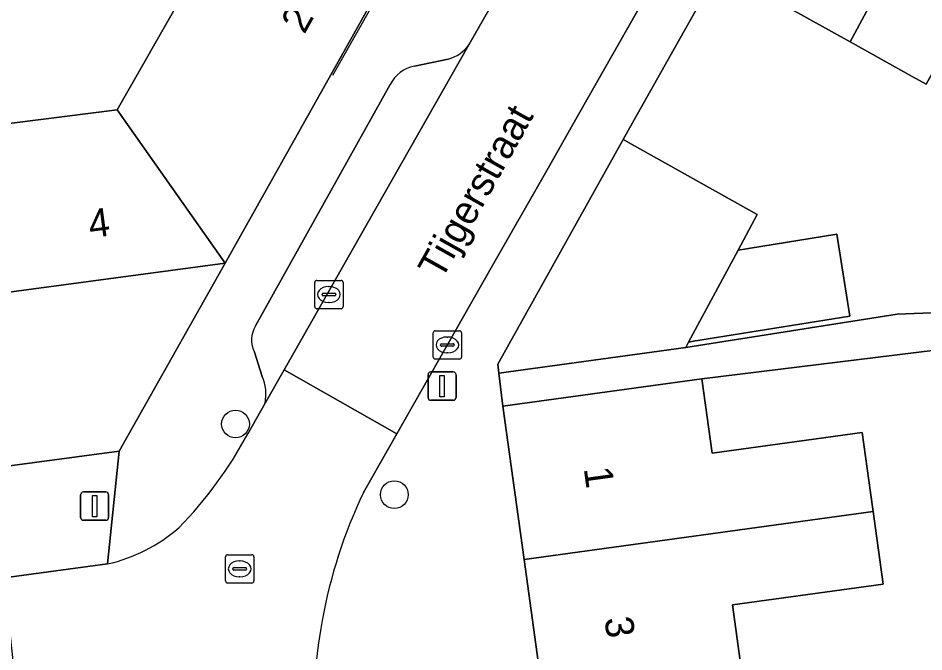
# Model space of a CAD drawing. Extents: x 163147 to 163550, y 380933 to 381639.
# Drawn here: x 163383.31 to 163415.28, y 381494.38 to 381516.74 of the extents above; entities that cross this region are included whole.
import ezdxf

# ---------------------------------------------------------------- set-up
doc = ezdxf.new("R2010")
doc.units = 0
for name, color, linetype in [('IMGEO_Boom', 7, 'Continuous'), ('IMGEO_Erf', 7, 'Continuous'), ('IMGEO_Kolk', 7, 'Continuous'), ('IMGEO_Lichtmast', 7, 'Continuous'), ('IMGEO_Muur', 7, 'Continuous'), ('IMGEO_Openbare_ruimte_label', 7, 'Continuous'), ('IMGEO_Pand', 7, 'Continuous'), ('IMGEO_Pand_nummerreeks', 7, 'Continuous'), ('IMGEO_Parkeervlak_open', 7, 'Continuous'), ('IMGEO_Rijbaan_lokaal_open', 7, 'Continuous'), ('IMGEO_Rioolput', 7, 'Continuous'), ('IMGEO_Voetpad_open', 7, 'Continuous')]:
    doc.layers.add(name, color=color, linetype=linetype)

msp = doc.modelspace()

# ---------------------------------------------------------------- linework, layer by layer
at = {"layer": 'IMGEO_Boom'}
for centre in [(163390.984, 381502.417), (163396.588, 381499.924)]:
    msp.add_circle(centre, 0.489, dxfattribs=at)
at = {"layer": 'IMGEO_Erf'}
for points in [[(163290.692, 381502.077), (163296.934, 381502.909), (163303.175, 381503.742), (163309.37, 381504.568), (163317.378, 381505.636), (163320.439, 381506.043), (163328.504, 381507.143), (163334.606, 381507.974), (163340.83, 381508.823), (163347.054, 381509.671), (163353.278, 381510.52), (163359.502, 381511.368), (163365.726, 381512.217), (163371.951, 381513.065), (163378.25, 381513.924), (163378.437, 381512.446), (163386.81, 381513.506), (163391.494, 381521.713), (163396.616, 381518.793), (163399.995, 381524.821), (163394.095, 381528.2), (163395.21, 381530.178), (163389.772, 381533.219)], [(163410.272, 381522.434), (163405.156, 381513.335), (163404.666, 381512.456), (163409.399, 381509.817), (163408.72, 381508.556), (163409.018, 381508.603), (163409.088, 381508.615), (163412.202, 381509.113), (163412.665, 381506.223), (163407.37, 381505.375), (163407.307, 381505.365), (163407.203, 381505.348), (163406.974, 381505.312), (163406.872, 381505.122), (163407.094, 381505.153), (163414.331, 381506.299), (163417.656, 381506.427)], [(163418.659, 381520.343), (163415.352, 381514.411), (163414.86, 381514.686), (163412.675, 381515.904), (163410.492, 381517.121)], [(163386.878, 381501.46), (163390.622, 381508.099), (163381.921, 381506.929), (163382.408, 381503.275), (163379.644, 381502.906), (163373.418, 381502.075), (163367.191, 381501.244), (163360.965, 381500.413), (163354.738, 381499.581), (163348.512, 381498.75), (163342.285, 381497.919), (163336.059, 381497.088), (163336.166, 381496.323), (163331.126, 381495.675), (163330.852, 381497.601), (163329.792, 381497.46), (163321.723, 381496.388), (163321.893, 381494.988), (163321.919, 381494.8)], [(163416.346, 381505.106), (163407.444, 381504.011), (163407.806, 381501.386), (163413.097, 381502.115), (163413.393, 381500), (163413.486, 381499.333), (163413.844, 381496.769), (163408.52, 381496.035), (163408.91, 381493.202), (163413.394, 381493.954), (163419.82, 381493.713)], [(163323.398, 381493.128), (163323.846, 381493.024), (163386.878, 381501.46)]]:
    msp.add_lwpolyline(points, dxfattribs=at)
at = {"layer": 'IMGEO_Kolk'}
for p, q in [((163393.781, 381506.561), (163393.781, 381507.413)), ((163393.856, 381507.487), (163394.708, 381507.487)), ((163394.782, 381507.413), (163394.782, 381506.561)), ((163394.269, 381507.267), (163394.294, 381507.267)), ((163394.04, 381506.981), (163394.04, 381506.993)), ((163394.478, 381506.944), (163394.08, 381506.944)), ((163394.083, 381507.03), (163394.481, 381507.03)), ((163394.524, 381506.993), (163394.524, 381506.981)), ((163394.708, 381506.487), (163393.856, 381506.487)), ((163394.292, 381506.707), (163394.267, 381506.707)), ((163397.961, 381504.782), (163397.961, 381505.634)), ((163398.036, 381505.708), (163398.888, 381505.708)), ((163398.449, 381505.488), (163398.474, 381505.488)), ((163398.962, 381505.634), (163398.962, 381504.782)), ((163398.22, 381505.202), (163398.22, 381505.214)), ((163398.658, 381505.165), (163398.26, 381505.165)), ((163398.263, 381505.251), (163398.661, 381505.251)), ((163398.704, 381505.214), (163398.704, 381505.202)), ((163398.472, 381504.928), (163398.447, 381504.928)), ((163398.888, 381504.708), (163398.036, 381504.708))]:
    msp.add_line(p, q, dxfattribs=at)
for points in [[(163393.781, 381506.561), (163393.781, 381507.413)], [(163393.856, 381507.487), (163394.708, 381507.487)], [(163394.782, 381507.413), (163394.782, 381506.561)], [(163394.708, 381506.487), (163393.856, 381506.487)], [(163397.961, 381504.782), (163397.961, 381505.634)], [(163398.036, 381505.708), (163398.888, 381505.708)], [(163398.962, 381505.634), (163398.962, 381504.782)], [(163398.888, 381504.708), (163398.036, 381504.708)]]:
    msp.add_lwpolyline(points, dxfattribs=at)
for centre, radius, start, end in [((163393.858, 381507.411), 0.0765, 91.552, 178.448), ((163393.858, 381507.411), 0.0765, 91.552, 178.448), ((163394.706, 381507.411), 0.0765, 1.552, 88.448), ((163394.706, 381507.411), 0.0765, 1.552, 88.448), ((163394.08, 381506.99), 0.0403, 85.8775, 175.7526), ((163394.077, 381506.98), 0.0366, 178.938, 274.7102), ((163394.481, 381506.987), 0.043, 264.8664, 352.4533), ((163394.485, 381506.992), 0.0386, 1.7309, 96.639), ((163393.858, 381506.563), 0.0765, 181.552, 268.448), ((163393.858, 381506.563), 0.0765, 181.552, 268.448), ((163394.706, 381506.563), 0.0765, 271.552, 358.448), ((163394.706, 381506.563), 0.0765, 271.552, 358.448), ((163398.038, 381505.632), 0.0765, 91.552, 178.448), ((163398.038, 381505.632), 0.0765, 91.552, 178.448), ((163398.886, 381505.632), 0.0765, 1.552, 88.448), ((163398.886, 381505.632), 0.0765, 1.552, 88.448), ((163398.26, 381505.211), 0.0403, 85.8775, 175.7526), ((163398.257, 381505.201), 0.0366, 178.938, 274.7102), ((163398.661, 381505.208), 0.043, 264.8664, 352.4533), ((163398.665, 381505.213), 0.0386, 1.7309, 96.639), ((163398.038, 381504.784), 0.0765, 181.552, 268.448), ((163398.038, 381504.784), 0.0765, 181.552, 268.448), ((163398.886, 381504.784), 0.0765, 271.552, 358.448), ((163398.886, 381504.784), 0.0765, 271.552, 358.448)]:
    msp.add_arc(centre, radius, start, end, dxfattribs=at)
for centre, major_axis, ratio, start_param, end_param in [((163394.268, 381506.987), (-0.387, 0.002), 0.722429, 4.712389, 7.853982), ((163394.293, 381506.987), (-0.39, 0.002), 0.717154, 1.570796, 4.712389), ((163398.448, 381505.208), (-0.387, 0.002), 0.722429, 4.712389, 7.853982), ((163398.473, 381505.208), (-0.39, 0.002), 0.717154, 1.570796, 4.712389)]:
    msp.add_ellipse(centre, major_axis=major_axis, ratio=ratio, start_param=start_param, end_param=end_param, dxfattribs=at)
at = {"layer": 'IMGEO_Lichtmast'}
for p, q in [((163397.881, 381504.256), (163398.671, 381504.256)), ((163398.671, 381504.256), (163397.881, 381504.256)), ((163397.781, 381503.356), (163397.781, 381504.156)), ((163397.781, 381504.156), (163397.781, 381503.356)), ((163398.771, 381504.156), (163398.771, 381503.356)), ((163398.771, 381503.356), (163398.771, 381504.156)), ((163398.671, 381503.256), (163397.881, 381503.256)), ((163397.881, 381503.256), (163398.671, 381503.256)), ((163385.516, 381499.121), (163385.516, 381499.921)), ((163385.516, 381499.921), (163385.516, 381499.121)), ((163385.616, 381500.021), (163386.406, 381500.021)), ((163386.406, 381500.021), (163385.616, 381500.021)), ((163386.506, 381499.921), (163386.506, 381499.121)), ((163386.506, 381499.121), (163386.506, 381499.921)), ((163386.406, 381499.021), (163385.616, 381499.021)), ((163385.616, 381499.021), (163386.406, 381499.021))]:
    msp.add_line(p, q, dxfattribs=at)
for points in [[(163398.201, 381504.131), (163398.351, 381504.131), (163398.351, 381503.381), (163398.201, 381503.381), (163398.201, 381504.131)], [(163385.936, 381499.896), (163386.086, 381499.896), (163386.086, 381499.146), (163385.936, 381499.146), (163385.936, 381499.896)]]:
    msp.add_lwpolyline(points, dxfattribs=at)
for centre, start, end in [((163397.881, 381504.156), 90, 180), ((163397.881, 381504.156), 90, 180), ((163398.671, 381504.156), 0, 90), ((163398.671, 381504.156), 360, 90), ((163397.881, 381503.356), 180, 270), ((163397.881, 381503.356), 180, 270), ((163398.671, 381503.356), 270, 0), ((163398.671, 381503.356), 270, 0), ((163385.616, 381499.921), 90, 180), ((163385.616, 381499.921), 90, 180), ((163386.406, 381499.921), 0, 90), ((163386.406, 381499.921), 360, 90), ((163385.616, 381499.121), 180, 270), ((163385.616, 381499.121), 180, 270), ((163386.406, 381499.121), 270, 0), ((163386.406, 381499.121), 270, 0)]:
    msp.add_arc(centre, 0.1, start, end, dxfattribs=at)
at = {"layer": 'IMGEO_Muur'}
for points in [[(163405.156, 381513.335), (163410.272, 381522.434)], [(163394.422, 381514.725), (163396.264, 381518.003)]]:
    msp.add_lwpolyline(points, dxfattribs=at)
at = {"layer": 'IMGEO_Pand'}
for points in [[(163412.675, 381515.904), (163418.679, 381527.058), (163414.231, 381529.537), (163410.272, 381522.434), (163412.7, 381521.08), (163410.492, 381517.121)], [(163418.679, 381527.058), (163412.675, 381515.904), (163414.86, 381514.686), (163415.352, 381514.411), (163418.659, 381520.343), (163421.229, 381518.91), (163425.443, 381526.737), (163420.55, 381529.464), (163419.083, 381526.833)], [(163396.616, 381518.793), (163391.494, 381521.713), (163386.81, 381513.506), (163390.622, 381508.099)], [(163386.81, 381513.506), (163378.437, 381512.446), (163379.644, 381502.906), (163382.408, 381503.275), (163381.921, 381506.929), (163390.622, 381508.099)], [(163404.666, 381512.456), (163400.246, 381504.532), (163400.279, 381504.213), (163406.872, 381505.122), (163406.974, 381505.312), (163408.72, 381508.556), (163409.399, 381509.817)], [(163408.72, 381508.556), (163406.974, 381505.312), (163407.203, 381505.348), (163407.307, 381505.365), (163407.37, 381505.375), (163412.665, 381506.223), (163412.202, 381509.113), (163409.088, 381508.615), (163409.018, 381508.603)], [(163401.169, 381497.642), (163413.486, 381499.333), (163413.393, 381500), (163413.097, 381502.115), (163407.806, 381501.386), (163407.444, 381504.011), (163405.378, 381503.726), (163400.424, 381503.043), (163400.844, 381500)], [(163401.169, 381497.642), (163401.915, 381492.238), (163406.869, 381492.921), (163408.91, 381493.202), (163408.52, 381496.035), (163413.844, 381496.769), (163413.486, 381499.333)]]:
    msp.add_lwpolyline(points, close=True, dxfattribs=at)
at = {"layer": 'IMGEO_Parkeervlak_open'}
for points in [[(163392.026, 381503.156), (163392.697, 381504.335), (163399.217, 381515.793)], [(163398.491, 381515.293), (163397.3, 381515.05)], [(163396.445, 381514.395), (163391.695, 381505.878)], [(163391.651, 381504.952), (163391.925, 381504.1)]]:
    msp.add_lwpolyline(points, dxfattribs=at)
for centre, radius, start, end in [((163398.137, 381516.585), 1.339, 285.3429, 323.7679), ((163397.524, 381513.872), 1.199, 100.7741, 154.1361), ((163392.49, 381505.376), 0.941, 147.7537, 206.8055), ((163390.557, 381503.476), 1.503, 347.6991, 24.5148)]:
    msp.add_arc(centre, radius, start, end, dxfattribs=at)
at = {"layer": 'IMGEO_Rijbaan_lokaal_open'}
msp.add_lwpolyline([(163414.262, 381532.989), (163414.654, 381533.678), (163410.599, 381535.956), (163409.219, 381533.373), (163408.677, 381532.42), (163400.477, 381518.009), (163399.217, 381515.793), (163392.697, 381504.335), (163396.678, 381502.07), (163399.031, 381506.208), (163400.059, 381508.016), (163402.013, 381511.452), (163403.04, 381513.257)], close=True, dxfattribs=at)
for points in [[(163395.5, 381500), (163396.678, 381502.07), (163392.697, 381504.335), (163392.026, 381503.156), (163391.416, 381502.077)], [(163386.472, 381497.48), (163382.998, 381497.011), (163382.807, 381497.014), (163383.176, 381493.641), (163384.906, 381493.688)]]:
    msp.add_lwpolyline(points, dxfattribs=at)
for centre, radius, start, end in [((163378.756, 381508.8), 14.335, 315.5111, 332.0291), ((163411.836, 381492.225), 18.092, 154.5483, 184.6632), ((163385.108, 381503.273), 5.952, 283.2481, 310.6101)]:
    msp.add_arc(centre, radius, start, end, dxfattribs=at)
at = {"layer": 'IMGEO_Rioolput'}
for p, q in [((163390.706, 381497.806), (163391.558, 381497.806)), ((163390.631, 381496.88), (163390.631, 381497.732)), ((163391.119, 381497.586), (163391.144, 381497.586)), ((163391.632, 381497.732), (163391.632, 381496.88)), ((163390.89, 381497.3), (163390.89, 381497.312)), ((163391.328, 381497.263), (163390.93, 381497.263)), ((163390.933, 381497.349), (163391.331, 381497.349)), ((163391.374, 381497.312), (163391.374, 381497.3)), ((163391.142, 381497.026), (163391.117, 381497.026)), ((163391.558, 381496.806), (163390.706, 381496.806))]:
    msp.add_line(p, q, dxfattribs=at)
for points in [[(163390.706, 381497.806), (163391.558, 381497.806)], [(163390.631, 381496.88), (163390.631, 381497.732)], [(163391.632, 381497.732), (163391.632, 381496.88)], [(163391.558, 381496.806), (163390.706, 381496.806)]]:
    msp.add_lwpolyline(points, dxfattribs=at)
for centre, radius, start, end in [((163390.708, 381497.73), 0.0765, 91.552, 178.448), ((163390.708, 381497.73), 0.0765, 91.552, 178.448), ((163391.556, 381497.73), 0.0765, 1.552, 88.448), ((163391.556, 381497.73), 0.0765, 1.552, 88.448), ((163390.93, 381497.309), 0.0403, 85.8775, 175.7526), ((163390.927, 381497.299), 0.0366, 178.938, 274.7102), ((163391.331, 381497.306), 0.043, 264.8664, 352.4533), ((163391.335, 381497.311), 0.0386, 1.7309, 96.639), ((163390.708, 381496.882), 0.0765, 181.552, 268.448), ((163390.708, 381496.882), 0.0765, 181.552, 268.448), ((163391.556, 381496.882), 0.0765, 271.552, 358.448), ((163391.556, 381496.882), 0.0765, 271.552, 358.448)]:
    msp.add_arc(centre, radius, start, end, dxfattribs=at)
for centre, major_axis, ratio, start_param, end_param in [((163391.118, 381497.306), (-0.387, 0.002), 0.722429, 4.712389, 7.853982), ((163391.143, 381497.306), (-0.39, 0.002), 0.717154, 1.570796, 4.712389)]:
    msp.add_ellipse(centre, major_axis=major_axis, ratio=ratio, start_param=start_param, end_param=end_param, dxfattribs=at)
at = {"layer": 'IMGEO_Voetpad_open'}
for points in [[(163408.677, 381532.42), (163409.219, 381533.373), (163410.599, 381535.956), (163406.822, 381537.075), (163405.373, 381534.442), (163399.995, 381524.821), (163396.616, 381518.793), (163390.622, 381508.099), (163386.878, 381501.46), (163386.472, 381497.48)], [(163414.231, 381529.537), (163415.715, 381532.175), (163417.612, 381535.547), (163416.384, 381536.72), (163414.654, 381533.678), (163414.262, 381532.989), (163403.04, 381513.257), (163402.013, 381511.452), (163400.059, 381508.016), (163399.031, 381506.208), (163396.678, 381502.07), (163395.5, 381500)], [(163393.804, 381490.754), (163396.932, 381490.11), (163399.443, 381490.376), (163402.139, 381490.739), (163401.915, 381492.238), (163401.169, 381497.642), (163400.844, 381500), (163400.424, 381503.043), (163400.279, 381504.213), (163400.246, 381504.532), (163404.666, 381512.456), (163405.156, 381513.335), (163410.272, 381522.434), (163414.231, 381529.537)], [(163399.217, 381515.793), (163400.477, 381518.009)], [(163397.3, 381515.05), (163398.491, 381515.293)], [(163391.695, 381505.878), (163396.445, 381514.395)], [(163391.925, 381504.1), (163391.651, 381504.952)], [(163391.416, 381502.077), (163392.026, 381503.156)], [(163386.878, 381501.46), (163323.846, 381493.024), (163319.114, 381492.391), (163317.206, 381492.135), (163261.264, 381484.648), (163258.765, 381484.37)], [(163382.807, 381497.014), (163382.998, 381497.011), (163386.472, 381497.48), (163386.878, 381501.46)]]:
    msp.add_lwpolyline(points, dxfattribs=at)
msp.add_lwpolyline([(163416.346, 381505.106), (163421.576, 381502.441), (163422.267, 381503.814), (163419.867, 381505.174), (163417.656, 381506.427), (163414.331, 381506.299), (163407.094, 381505.153), (163406.872, 381505.122), (163400.279, 381504.213), (163400.424, 381503.043), (163405.378, 381503.726), (163407.444, 381504.011)], close=True, dxfattribs=at)
for centre, radius, start, end in [((163398.137, 381516.585), 1.339, 285.3429, 323.7679), ((163397.524, 381513.872), 1.199, 100.7741, 154.1361), ((163392.49, 381505.376), 0.941, 147.7537, 206.8055), ((163390.557, 381503.476), 1.503, 347.6991, 24.5148), ((163378.756, 381508.8), 14.335, 315.5111, 332.0291), ((163411.836, 381492.225), 18.092, 154.5483, 184.6632), ((163385.108, 381503.273), 5.952, 283.2481, 310.6101)]:
    msp.add_arc(centre, radius, start, end, dxfattribs=at)

# ---------------------------------------------------------------- texts
at = {"layer": 'IMGEO_Openbare_ruimte_label'}
msp.add_text('Tijgerstraat', height=1, rotation=60.7172, dxfattribs=at).set_placement((163398.252, 381507.467))
at = {"layer": 'IMGEO_Pand_nummerreeks'}
for s, rotation, p in [('2', 60.7278, (163393.413, 381516.146)), ('4', 7.6604, (163385.861, 381508.972)), ('1', 277.8537, (163403.272, 381500.848)), ('3', 277.8598, (163404.001, 381495.557))]:
    msp.add_text(s, height=1, rotation=rotation, dxfattribs=at).set_placement(p)

doc.saveas('drawing.dxf')
